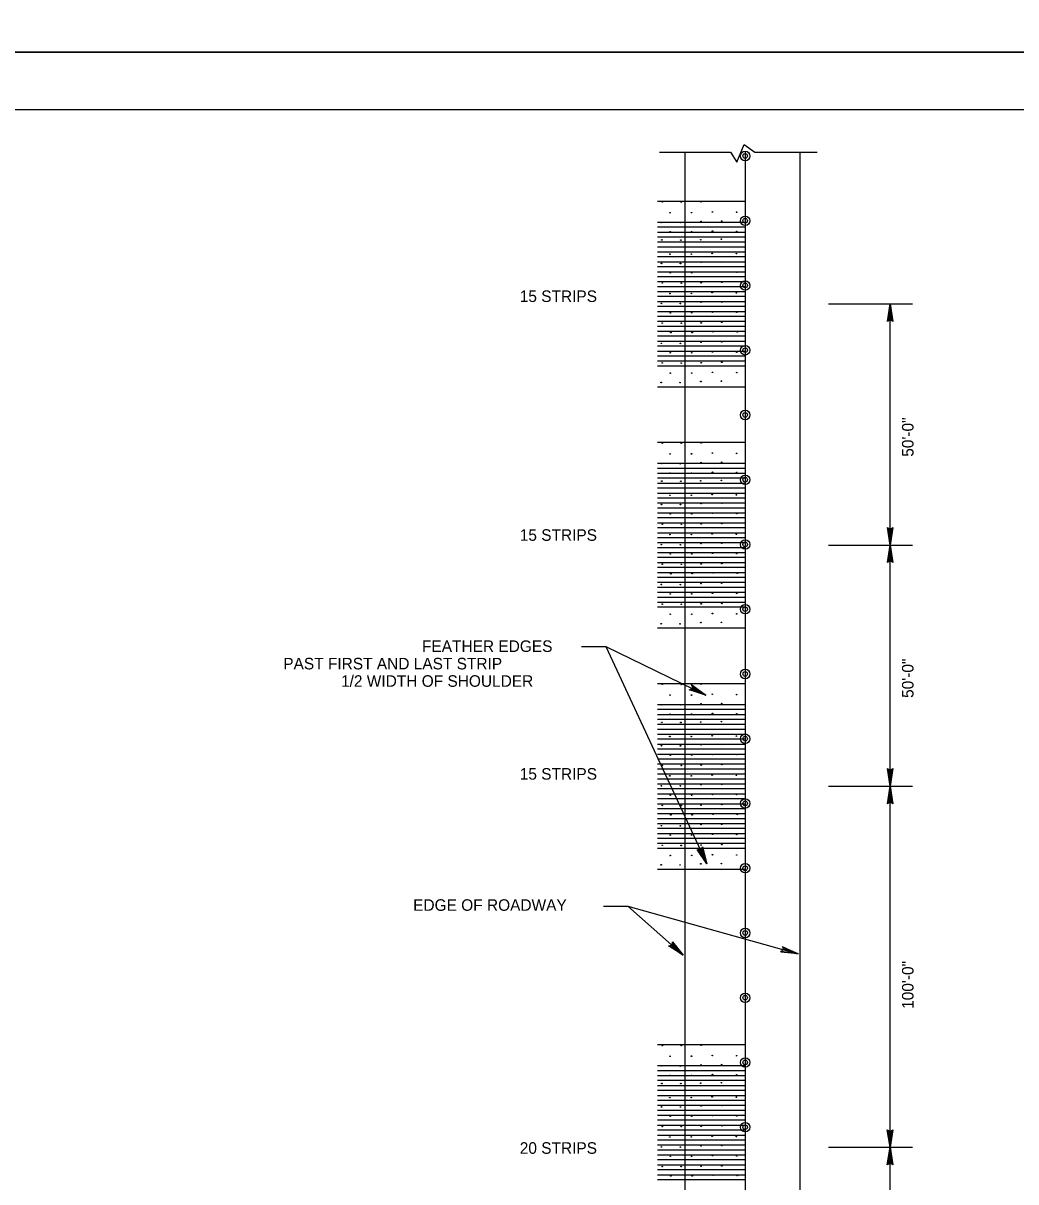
# Model space of a CAD drawing. Extents: x 632008 to 634206, y 294231 to 297795.
# Drawn here: x 632265.7 to 632523.5, y 294531.2 to 294832.1 of the extents above; entities that cross this region are included whole.
import ezdxf

# ---------------------------------------------------------------- set-up
doc = ezdxf.new("R2010")
doc.units = 0
for name, color, linetype in [('1', 7, 'Continuous'), ('Level 2', 7, 'Continuous'), ('Level 3', 7, 'Continuous'), ('PLT-BNDY', 7, 'Continuous')]:
    doc.layers.add(name, color=color, linetype=linetype)

msp = doc.modelspace()

# ---------------------------------------------------------------- linework, layer by layer
at = {"layer": '1'}
msp.add_lwpolyline([(632833.86, 294245.62), (632833.86, 294809.62), (632047.86, 294809.62), (632047.86, 294245.62), (632833.86, 294245.62), (632833.86, 294271.98), (632633.86, 294271.98), (632633.86, 294336.66), (632833.86, 294336.66), (632833.86, 294365.62), (632633.86, 294365.62), (632633.86, 294245.62), (632712.66, 294245.62), (632712.66, 294271.98), (632712.66, 294245.62), (632789.66, 294245.62), (632789.66, 294271.98), (632789.66, 294259.66), (632833.86, 294259.66)], dxfattribs=at)
at = {"layer": 'Level 2'}
for p, q in [((632437.46, 294798.64), (632437.46, 294287.23)), ((632453.13, 294798.64), (632453.17, 294284.41)), ((632467.47, 294287.23), (632467.47, 294798.64)), ((632430.37, 294785.92), (632453.13, 294785.92)), ((632430.37, 294780.45), (632453.13, 294780.45)), ((632430.37, 294779.21), (632453.13, 294779.21)), ((632430.37, 294777.88), (632453.13, 294777.88)), ((632430.37, 294776.64), (632453.13, 294776.64)), ((632430.37, 294775.3), (632453.13, 294775.3)), ((632430.37, 294774.06), (632453.13, 294774.06)), ((632430.37, 294772.72), (632453.13, 294772.72)), ((632430.37, 294771.48), (632453.13, 294771.48)), ((632430.37, 294770.15), (632453.13, 294770.15)), ((632430.37, 294768.91), (632453.13, 294768.91)), ((632430.37, 294767.57), (632453.13, 294767.57)), ((632430.37, 294766.33), (632453.13, 294766.33)), ((632430.37, 294764.99), (632453.13, 294764.99)), ((632430.37, 294763.75), (632453.13, 294763.75)), ((632430.37, 294762.42), (632453.13, 294762.42)), ((632430.37, 294761.18), (632453.13, 294761.18)), ((632430.37, 294759.84), (632453.13, 294759.84)), ((632430.37, 294758.6), (632453.13, 294758.6)), ((632474.85, 294759.23), (632496.62, 294759.23)), ((632490.81, 294696.58), (632490.81, 294759.23)), ((632430.37, 294757.26), (632453.13, 294757.26)), ((632430.37, 294756.02), (632453.13, 294756.02)), ((632430.37, 294754.69), (632453.13, 294754.69)), ((632430.37, 294753.45), (632453.13, 294753.45)), ((632430.37, 294752.11), (632453.13, 294752.11)), ((632430.37, 294750.87), (632453.13, 294750.87)), ((632430.37, 294749.53), (632453.13, 294749.53)), ((632430.37, 294748.29), (632453.13, 294748.29)), ((632430.37, 294746.96), (632453.13, 294746.96)), ((632430.37, 294745.72), (632453.13, 294745.72)), ((632430.37, 294744.38), (632453.14, 294744.38)), ((632430.37, 294743.14), (632453.14, 294743.14)), ((632430.37, 294737.68), (632453.14, 294737.68)), ((632430.37, 294723.27), (632453.13, 294723.27)), ((632430.37, 294717.81), (632453.13, 294717.81)), ((632430.37, 294716.57), (632453.13, 294716.57)), ((632430.37, 294715.23), (632453.13, 294715.23)), ((632430.37, 294713.99), (632453.13, 294713.99)), ((632430.37, 294712.65), (632453.13, 294712.65)), ((632430.37, 294711.41), (632453.13, 294711.41)), ((632430.37, 294710.08), (632453.13, 294710.08)), ((632430.37, 294708.84), (632453.13, 294708.84)), ((632430.37, 294707.5), (632453.13, 294707.5)), ((632430.37, 294706.26), (632453.13, 294706.26)), ((632430.37, 294704.92), (632453.13, 294704.92)), ((632430.37, 294703.68), (632453.13, 294703.68)), ((632430.37, 294702.35), (632453.13, 294702.35)), ((632430.37, 294701.11), (632453.13, 294701.11)), ((632430.37, 294699.77), (632453.13, 294699.77)), ((632430.37, 294698.53), (632453.13, 294698.53)), ((632430.37, 294697.19), (632453.13, 294697.19)), ((632430.37, 294695.95), (632453.13, 294695.95)), ((632474.85, 294696.58), (632496.62, 294696.58)), ((632490.81, 294633.93), (632490.81, 294696.58)), ((632430.37, 294694.62), (632453.13, 294694.62)), ((632430.37, 294693.38), (632453.13, 294693.38)), ((632430.37, 294692.04), (632453.13, 294692.04)), ((632430.37, 294690.8), (632453.13, 294690.8)), ((632430.37, 294689.46), (632453.13, 294689.46)), ((632430.37, 294688.22), (632453.13, 294688.22)), ((632430.37, 294686.89), (632453.13, 294686.89)), ((632430.37, 294685.65), (632453.13, 294685.65)), ((632430.37, 294684.31), (632453.13, 294684.31)), ((632430.37, 294683.07), (632453.13, 294683.07)), ((632430.37, 294681.73), (632453.14, 294681.73)), ((632430.37, 294680.49), (632453.14, 294680.49)), ((632430.37, 294675.03), (632453.14, 294675.03)), ((632410.64, 294670.19), (632416.96, 294670.19)), ((632416.96, 294670.19), (632442.97, 294657.61)), ((632416.96, 294670.19), (632443.25, 294613.73)), ((632430.37, 294660.62), (632453.13, 294660.62)), ((632430.37, 294655.16), (632453.13, 294655.16)), ((632430.37, 294653.92), (632453.13, 294653.92)), ((632430.37, 294652.58), (632453.13, 294652.58)), ((632430.37, 294651.34), (632453.13, 294651.34)), ((632430.37, 294650.01), (632453.13, 294650.01)), ((632430.37, 294648.77), (632453.13, 294648.77)), ((632430.37, 294647.43), (632453.13, 294647.43)), ((632430.37, 294646.19), (632453.13, 294646.19)), ((632430.37, 294644.85), (632453.13, 294644.85)), ((632430.37, 294643.61), (632453.13, 294643.61)), ((632430.37, 294642.28), (632453.13, 294642.28)), ((632430.37, 294641.04), (632453.13, 294641.04)), ((632430.37, 294639.7), (632453.13, 294639.7)), ((632430.37, 294638.46), (632453.13, 294638.46)), ((632430.37, 294637.12), (632453.13, 294637.12)), ((632430.37, 294635.88), (632453.13, 294635.88)), ((632430.37, 294634.55), (632453.13, 294634.55)), ((632430.37, 294633.31), (632453.13, 294633.31)), ((632430.37, 294631.97), (632453.13, 294631.97)), ((632474.84, 294633.93), (632496.61, 294633.93)), ((632490.81, 294540.43), (632490.81, 294634.4)), ((632430.37, 294630.73), (632453.13, 294630.73)), ((632430.37, 294629.39), (632453.13, 294629.39)), ((632430.37, 294628.15), (632453.13, 294628.15)), ((632430.37, 294626.82), (632453.13, 294626.82)), ((632430.37, 294625.58), (632453.13, 294625.58)), ((632430.37, 294624.24), (632453.13, 294624.24)), ((632430.37, 294623), (632453.13, 294623)), ((632430.37, 294621.66), (632453.13, 294621.66)), ((632430.37, 294620.42), (632453.13, 294620.42)), ((632430.37, 294619.09), (632453.13, 294619.09)), ((632430.37, 294617.85), (632453.13, 294617.85)), ((632430.37, 294612.38), (632453.13, 294612.38)), ((632416.39, 294602.8), (632422.71, 294602.8)), ((632422.71, 294602.8), (632437.11, 294590)), ((632422.71, 294602.8), (632466.95, 294590.35)), ((632430.37, 294566.82), (632453.13, 294566.82)), ((632430.37, 294561.36), (632453.13, 294561.36)), ((632430.37, 294560.12), (632453.13, 294560.12)), ((632430.37, 294558.78), (632453.13, 294558.78)), ((632430.37, 294557.54), (632453.13, 294557.54)), ((632430.37, 294556.2), (632453.13, 294556.2)), ((632430.37, 294554.96), (632453.13, 294554.96)), ((632430.37, 294553.63), (632453.13, 294553.63)), ((632430.37, 294552.39), (632453.13, 294552.39)), ((632430.37, 294551.05), (632453.13, 294551.05)), ((632430.37, 294549.81), (632453.13, 294549.81)), ((632430.37, 294548.47), (632453.13, 294548.47)), ((632430.37, 294547.23), (632453.13, 294547.23)), ((632430.37, 294545.9), (632453.13, 294545.9)), ((632430.37, 294544.66), (632453.13, 294544.66)), ((632430.37, 294543.32), (632453.13, 294543.32)), ((632430.37, 294542.08), (632453.13, 294542.08)), ((632430.37, 294540.74), (632453.13, 294540.74)), ((632430.37, 294539.5), (632453.13, 294539.5)), ((632474.84, 294540.13), (632496.61, 294540.13)), ((632490.81, 294446.46), (632490.81, 294540.43)), ((632430.37, 294538.17), (632453.13, 294538.17)), ((632430.37, 294536.93), (632453.13, 294536.93)), ((632430.37, 294535.59), (632453.13, 294535.59)), ((632430.37, 294534.35), (632453.13, 294534.35)), ((632430.37, 294533.01), (632453.13, 294533.01)), ((632430.37, 294531.77), (632453.13, 294531.77))]:
    msp.add_line(p, q, dxfattribs=at)
for centre, radius in [((632453.17, 294797.62), 1.23), ((632453.17, 294797.63), 0.601), ((632431.66, 294785.68), 0.0832), ((632436.58, 294785.65), 0.0832), ((632441.74, 294785.75), 0.0832), ((632433.67, 294782.89), 0.0832), ((632439.23, 294782.9), 0.0832), ((632444.65, 294783.09), 0.0832), ((632450.94, 294783.02), 0.0832), ((632431.4, 294780.36), 0.0832), ((632436.33, 294780.33), 0.0832), ((632441.71, 294780.63), 0.0832), ((632447.06, 294780.7), 0.0832), ((632453.17, 294780.8), 1.23), ((632453.17, 294780.81), 0.601), ((632433.7, 294777.91), 0.0832), ((632439.26, 294777.93), 0.0832), ((632444.68, 294778.11), 0.0832), ((632450.97, 294778.04), 0.0832), ((632431.54, 294775.81), 0.0832), ((632436.46, 294775.78), 0.0832), ((632441.62, 294775.88), 0.0832), ((632447, 294776.01), 0.0832), ((632433.63, 294772.13), 0.0832), ((632439.19, 294772.14), 0.0832), ((632444.6, 294772.33), 0.0832), ((632447.09, 294770.08), 0.0832), ((632450.89, 294772.26), 0.0832), ((632431.43, 294769.73), 0.0832), ((632433.73, 294767.29), 0.0832), ((632436.36, 294769.7), 0.0832), ((632439.29, 294767.3), 0.0832), ((632441.74, 294770.01), 0.0832), ((632444.71, 294767.49), 0.0832), ((632451, 294767.42), 0.0832), ((632431.66, 294764.63), 0.0832), ((632436.58, 294764.6), 0.0832), ((632441.74, 294764.7), 0.0832), ((632447.12, 294764.82), 0.0832), ((632453.17, 294763.98), 1.23), ((632453.17, 294764), 0.601), ((632433.63, 294761.91), 0.0832), ((632439.19, 294761.93), 0.0832), ((632444.6, 294762.12), 0.0832), ((632450.89, 294762.04), 0.0832), ((632431.42, 294759.33), 0.0832), ((632436.34, 294759.3), 0.0832), ((632441.72, 294759.61), 0.0832), ((632447.08, 294759.68), 0.0832), ((632433.72, 294756.89), 0.0832), ((632439.28, 294756.9), 0.0832), ((632444.69, 294757.09), 0.0832), ((632450.98, 294757.02), 0.0832), ((632431.64, 294754.23), 0.0832), ((632436.57, 294754.2), 0.0832), ((632441.73, 294754.3), 0.0832), ((632447.1, 294754.43), 0.0832), ((632433.85, 294751.77), 0.0832), ((632439.41, 294751.79), 0.0832), ((632441.72, 294749.24), 0.0832), ((632444.83, 294751.98), 0.0832), ((632447.08, 294749.31), 0.0832), ((632451.12, 294751.91), 0.0832), ((632431.42, 294748.96), 0.0832), ((632433.72, 294746.52), 0.0832), ((632436.34, 294748.94), 0.0832), ((632439.28, 294746.53), 0.0832), ((632444.69, 294746.72), 0.0832), ((632450.98, 294746.65), 0.0832), ((632453.17, 294747.16), 1.23), ((632453.17, 294747.18), 0.601), ((632431.64, 294743.86), 0.0832), ((632436.57, 294743.83), 0.0832), ((632441.73, 294743.93), 0.0832), ((632447.1, 294744.06), 0.0832), ((632433.72, 294741.22), 0.0832), ((632439.28, 294741.24), 0.0832), ((632444.69, 294741.43), 0.0832), ((632450.98, 294741.36), 0.0832), ((632431.34, 294738.78), 0.0832), ((632436.27, 294738.75), 0.0832), ((632441.65, 294739.06), 0.0832), ((632447, 294739.13), 0.0832), ((632453.17, 294730.35), 1.23), ((632453.17, 294730.36), 0.601), ((632431.66, 294723.03), 0.0832), ((632431.66, 294723.03), 0.0832), ((632436.58, 294723.01), 0.0832), ((632436.58, 294723.01), 0.0832), ((632441.74, 294723.11), 0.0832), ((632441.74, 294723.11), 0.0832), ((632433.67, 294720.24), 0.0832), ((632439.23, 294720.26), 0.0832), ((632444.65, 294720.45), 0.0832), ((632450.94, 294720.37), 0.0832), ((632431.4, 294717.71), 0.0832), ((632436.33, 294717.68), 0.0832), ((632441.71, 294717.99), 0.0832), ((632447.06, 294718.06), 0.0832), ((632431.54, 294713.16), 0.0832), ((632433.7, 294715.26), 0.0832), ((632436.46, 294713.14), 0.0832), ((632439.26, 294715.28), 0.0832), ((632441.62, 294713.24), 0.0832), ((632444.68, 294715.47), 0.0832), ((632447, 294713.36), 0.0832), ((632450.97, 294715.4), 0.0832), ((632453.17, 294713.53), 1.23), ((632453.17, 294713.54), 0.601), ((632431.43, 294707.08), 0.0832), ((632433.63, 294709.48), 0.0832), ((632436.36, 294707.06), 0.0832), ((632439.19, 294709.49), 0.0832), ((632441.74, 294707.36), 0.0832), ((632444.6, 294709.68), 0.0832), ((632447.09, 294707.43), 0.0832), ((632450.89, 294709.61), 0.0832), ((632433.73, 294704.64), 0.0832), ((632439.29, 294704.65), 0.0832), ((632444.71, 294704.84), 0.0832), ((632451, 294704.77), 0.0832), ((632431.66, 294701.98), 0.0832), ((632436.58, 294701.95), 0.0832), ((632441.74, 294702.05), 0.0832), ((632447.12, 294702.18), 0.0832), ((632433.63, 294699.27), 0.0832), ((632439.19, 294699.28), 0.0832), ((632444.6, 294699.47), 0.0832), ((632450.89, 294699.4), 0.0832), ((632453.17, 294696.71), 1.23), ((632431.42, 294696.69), 0.0832), ((632436.34, 294696.66), 0.0832), ((632441.72, 294696.96), 0.0832), ((632447.08, 294697.03), 0.0832), ((632453.17, 294696.72), 0.601), ((632433.72, 294694.24), 0.0832), ((632439.28, 294694.26), 0.0832), ((632444.69, 294694.44), 0.0832), ((632450.98, 294694.37), 0.0832), ((632431.64, 294691.59), 0.0832), ((632433.85, 294689.13), 0.0832), ((632436.57, 294691.56), 0.0832), ((632439.41, 294689.14), 0.0832), ((632441.73, 294691.66), 0.0832), ((632444.83, 294689.33), 0.0832), ((632447.1, 294691.78), 0.0832), ((632451.12, 294689.26), 0.0832), ((632431.42, 294686.32), 0.0832), ((632436.34, 294686.29), 0.0832), ((632441.72, 294686.59), 0.0832), ((632447.08, 294686.66), 0.0832), ((632433.72, 294683.87), 0.0832), ((632439.28, 294683.89), 0.0832), ((632444.69, 294684.08), 0.0832), ((632450.98, 294684), 0.0832), ((632431.64, 294681.22), 0.0832), ((632436.57, 294681.19), 0.0832), ((632441.73, 294681.29), 0.0832), ((632447.1, 294681.41), 0.0832), ((632453.17, 294679.89), 1.23), ((632453.17, 294679.91), 0.601), ((632433.72, 294678.58), 0.0832), ((632439.28, 294678.59), 0.0832), ((632444.69, 294678.78), 0.0832), ((632450.98, 294678.71), 0.0832), ((632431.34, 294676.13), 0.0832), ((632436.27, 294676.1), 0.0832), ((632441.65, 294676.41), 0.0832), ((632447, 294676.48), 0.0832), ((632453.17, 294663.07), 1.23), ((632453.17, 294663.09), 0.601), ((632431.65, 294660.39), 0.0832), ((632431.65, 294660.39), 0.0832), ((632436.58, 294660.36), 0.0832), ((632436.58, 294660.36), 0.0832), ((632441.74, 294660.46), 0.0832), ((632441.74, 294660.46), 0.0832), ((632433.67, 294657.6), 0.0832), ((632439.23, 294657.61), 0.0832), ((632444.64, 294657.8), 0.0832), ((632450.94, 294657.73), 0.0832), ((632431.4, 294655.06), 0.0832), ((632436.33, 294655.03), 0.0832), ((632441.71, 294655.34), 0.0832), ((632444.67, 294652.82), 0.0832), ((632447.06, 294655.41), 0.0832), ((632450.97, 294652.75), 0.0832), ((632431.53, 294650.52), 0.0832), ((632433.7, 294652.62), 0.0832), ((632436.46, 294650.49), 0.0832), ((632439.26, 294652.63), 0.0832), ((632441.62, 294650.59), 0.0832), ((632446.99, 294650.71), 0.0832), ((632433.62, 294646.83), 0.0832), ((632439.18, 294646.85), 0.0832), ((632444.6, 294647.04), 0.0832), ((632450.89, 294646.96), 0.0832), ((632453.17, 294646.26), 1.23), ((632453.17, 294646.27), 0.601), ((632431.43, 294644.44), 0.0832), ((632436.36, 294644.41), 0.0832), ((632441.74, 294644.71), 0.0832), ((632447.09, 294644.78), 0.0832), ((632433.73, 294641.99), 0.0832), ((632439.29, 294642.01), 0.0832), ((632444.7, 294642.2), 0.0832), ((632451, 294642.12), 0.0832), ((632431.65, 294639.34), 0.0832), ((632436.58, 294639.31), 0.0832), ((632441.74, 294639.41), 0.0832), ((632447.11, 294639.53), 0.0832), ((632433.62, 294636.62), 0.0832), ((632439.18, 294636.63), 0.0832), ((632444.6, 294636.82), 0.0832), ((632450.89, 294636.75), 0.0832), ((632431.42, 294634.04), 0.0832), ((632436.34, 294634.01), 0.0832), ((632439.27, 294631.61), 0.0832), ((632441.72, 294634.32), 0.0832), ((632444.69, 294631.8), 0.0832), ((632447.07, 294634.39), 0.0832), ((632450.98, 294631.73), 0.0832), ((632431.64, 294628.94), 0.0832), ((632433.71, 294631.59), 0.0832), ((632436.56, 294628.91), 0.0832), ((632441.72, 294629.01), 0.0832), ((632447.1, 294629.13), 0.0832), ((632453.17, 294629.44), 1.23), ((632453.17, 294629.45), 0.601), ((632433.85, 294626.48), 0.0832), ((632439.41, 294626.49), 0.0832), ((632444.83, 294626.68), 0.0832), ((632451.12, 294626.61), 0.0832), ((632431.42, 294623.67), 0.0832), ((632436.34, 294623.64), 0.0832), ((632441.72, 294623.95), 0.0832), ((632447.07, 294624.02), 0.0832), ((632433.71, 294621.23), 0.0832), ((632439.27, 294621.24), 0.0832), ((632444.69, 294621.43), 0.0832), ((632450.98, 294621.36), 0.0832), ((632431.64, 294618.57), 0.0832), ((632436.56, 294618.54), 0.0832), ((632441.72, 294618.64), 0.0832), ((632447.1, 294618.76), 0.0832), ((632433.71, 294615.93), 0.0832), ((632439.28, 294615.95), 0.0832), ((632441.64, 294613.76), 0.0832), ((632444.69, 294616.13), 0.0832), ((632447, 294613.83), 0.0832), ((632450.98, 294616.06), 0.0832), ((632453.17, 294612.62), 1.23), ((632431.34, 294613.49), 0.0832), ((632436.27, 294613.46), 0.0832), ((632453.17, 294612.63), 0.601), ((632453.17, 294595.8), 1.23), ((632453.17, 294595.82), 0.601), ((632453.17, 294578.98), 1.23), ((632453.17, 294579), 0.601), ((632431.65, 294566.58), 0.0832), ((632431.65, 294566.58), 0.0832), ((632436.58, 294566.55), 0.0832), ((632436.58, 294566.55), 0.0832), ((632441.74, 294566.65), 0.0832), ((632441.74, 294566.65), 0.0832), ((632433.67, 294563.79), 0.0832), ((632439.23, 294563.81), 0.0832), ((632444.64, 294563.99), 0.0832), ((632450.94, 294563.92), 0.0832), ((632453.17, 294562.17), 1.23), ((632453.17, 294562.18), 0.601), ((632431.4, 294561.26), 0.0832), ((632436.33, 294561.23), 0.0832), ((632441.71, 294561.54), 0.0832), ((632447.06, 294561.61), 0.0832), ((632431.53, 294556.71), 0.0832), ((632433.7, 294558.81), 0.0832), ((632436.46, 294556.68), 0.0832), ((632439.26, 294558.83), 0.0832), ((632441.62, 294556.78), 0.0832), ((632444.67, 294559.02), 0.0832), ((632446.99, 294556.91), 0.0832), ((632450.97, 294558.95), 0.0832), ((632431.43, 294550.63), 0.0832), ((632433.62, 294553.03), 0.0832), ((632436.36, 294550.6), 0.0832), ((632439.18, 294553.04), 0.0832), ((632441.74, 294550.91), 0.0832), ((632444.6, 294553.23), 0.0832), ((632447.09, 294550.98), 0.0832), ((632450.89, 294553.16), 0.0832), ((632433.73, 294548.19), 0.0832), ((632439.29, 294548.2), 0.0832), ((632444.7, 294548.39), 0.0832), ((632451, 294548.32), 0.0832), ((632431.65, 294545.53), 0.0832), ((632436.58, 294545.5), 0.0832), ((632441.74, 294545.6), 0.0832), ((632447.11, 294545.73), 0.0832), ((632453.17, 294545.35), 1.23), ((632453.17, 294545.36), 0.601), ((632433.62, 294542.81), 0.0832), ((632439.18, 294542.83), 0.0832), ((632444.6, 294543.02), 0.0832), ((632450.89, 294542.95), 0.0832), ((632431.42, 294540.24), 0.0832), ((632436.34, 294540.21), 0.0832), ((632441.72, 294540.51), 0.0832), ((632447.07, 294540.58), 0.0832), ((632433.71, 294537.79), 0.0832), ((632439.27, 294537.81), 0.0832), ((632444.69, 294537.99), 0.0832), ((632447.1, 294535.33), 0.0832), ((632450.98, 294537.92), 0.0832), ((632431.64, 294535.13), 0.0832), ((632433.85, 294532.68), 0.0832), ((632436.56, 294535.11), 0.0832), ((632439.41, 294532.69), 0.0832), ((632441.72, 294535.21), 0.0832), ((632444.83, 294532.88), 0.0832), ((632451.12, 294532.81), 0.0832)]:
    msp.add_circle(centre, radius, dxfattribs=at)
at = {"layer": 'Level 3'}
for p, q in [((632450.97, 294796.01), (632452.91, 294800.58)), ((632452.91, 294800.58), (632455.72, 294798.64)), ((632430.96, 294798.64), (632449.4, 294798.64)), ((632449.4, 294798.64), (632450.97, 294796.01)), ((632455.72, 294798.64), (632471.88, 294798.64))]:
    msp.add_line(p, q, dxfattribs=at)
for points in [[(632490.3, 294754.85), (632490.65, 294755.01), (632490.81, 294759.23), (632490.3, 294754.85), (632490.11, 294754.66), (632490.81, 294759.23), (632491, 294755.01), (632491.35, 294754.85), (632490.81, 294759.23), (632491.51, 294754.66), (632491.35, 294754.85)], [(632491.35, 294700.98), (632491, 294700.79), (632490.81, 294696.58), (632491.35, 294700.98), (632491.51, 294701.14), (632490.81, 294696.58), (632490.65, 294700.79), (632490.3, 294700.98), (632490.81, 294696.58), (632490.11, 294701.14), (632490.3, 294700.98)], [(632490.3, 294692.2), (632490.65, 294692.36), (632490.81, 294696.58), (632490.3, 294692.2), (632490.11, 294692.01), (632490.81, 294696.58), (632491, 294692.36), (632491.35, 294692.2), (632490.81, 294696.58), (632491.51, 294692.01), (632491.35, 294692.2)], [(632439.33, 294659.96), (632439.39, 294659.62), (632442.97, 294657.61), (632439.33, 294659.96), (632439.26, 294660.31), (632442.97, 294657.61), (632439.27, 294659.24), (632438.95, 294659.02), (632442.97, 294657.61), (632438.61, 294658.95), (632438.95, 294659.02)], [(632491.35, 294638.33), (632491, 294638.15), (632490.81, 294633.93), (632491.35, 294638.33), (632491.51, 294638.5), (632490.81, 294633.93), (632490.65, 294638.15), (632490.3, 294638.33), (632490.81, 294633.93), (632490.11, 294638.5), (632490.3, 294638.33)], [(632490.3, 294629.55), (632490.65, 294629.72), (632490.81, 294633.93), (632490.3, 294629.55), (632490.11, 294629.37), (632490.81, 294633.93), (632491, 294629.72), (632491.35, 294629.55), (632490.81, 294633.93), (632491.51, 294629.37), (632491.35, 294629.55)], [(632441.95, 294617.82), (632441.69, 294617.53), (632443.25, 294613.73), (632441.95, 294617.82), (632442.06, 294618.15), (632443.25, 294613.73), (632441.31, 294617.48), (632440.92, 294617.41), (632443.25, 294613.73), (632440.74, 294617.46), (632440.92, 294617.41)], [(632434.3, 294593.16), (632434.13, 294592.97), (632437.11, 294590), (632434.3, 294593.16), (632434.3, 294593.51), (632437.11, 294590), (632433.95, 294592.62), (632433.59, 294592.46), (632437.11, 294590), (632433.24, 294592.46), (632433.59, 294592.46)], [(632462.93, 294592.1), (632462.93, 294591.75), (632466.95, 294590.35), (632462.93, 294592.1), (632462.74, 294592.27), (632466.95, 294590.35), (632462.93, 294591.4), (632462.57, 294591.05), (632466.95, 294590.35), (632462.39, 294590.86), (632462.57, 294591.05)], [(632491.33, 294544.53), (632490.98, 294544.34), (632490.79, 294540.13), (632491.33, 294544.53), (632491.49, 294544.69), (632490.79, 294540.13), (632490.63, 294544.34), (632490.28, 294544.53), (632490.79, 294540.13), (632490.09, 294544.69), (632490.28, 294544.53)], [(632490.28, 294535.75), (632490.63, 294535.91), (632490.79, 294540.13), (632490.28, 294535.75), (632490.09, 294535.56), (632490.79, 294540.13), (632490.98, 294535.91), (632491.33, 294535.75), (632490.79, 294540.13), (632491.49, 294535.56), (632491.33, 294535.75)]]:
    msp.add_lwpolyline(points, dxfattribs=at)
at = {"layer": 'PLT-BNDY'}
for points in [[(632007.86, 295418.62), (632848.86, 295418.62), (632848.86, 294824.62), (632007.86, 294824.62)], [(632007.86, 294824.62), (632848.86, 294824.62), (632848.86, 294230.62), (632007.86, 294230.62)]]:
    msp.add_lwpolyline(points, close=True, dxfattribs=at)

# ---------------------------------------------------------------- texts
at = {"layer": 'Level 2'}
for s, p in [('15 STRIPS', (632394.63, 294759.7)), ('15 STRIPS', (632394.63, 294697.67)), ('FEATHER EDGES', (632369.24, 294668.8)), ('PAST FIRST AND LAST STRIP', (632333.21, 294664.27)), ('1/2 WIDTH OF SHOULDER', (632348.21, 294659.75)), ('15 STRIPS', (632394.63, 294635.63)), ('EDGE OF ROADWAY', (632366.94, 294601.56)), ('20 STRIPS', (632394.63, 294538.45))]:
    msp.add_text(s, height=3, dxfattribs=at).set_placement(p)
for s, p in [('50\'-0"', (632496.9, 294719.5)), ('50\'-0"', (632496.9, 294656.86)), ('100\'-0"', (632496.9, 294576.09))]:
    msp.add_text(s, height=3, rotation=90, dxfattribs=at).set_placement(p)

doc.saveas('drawing.dxf')
